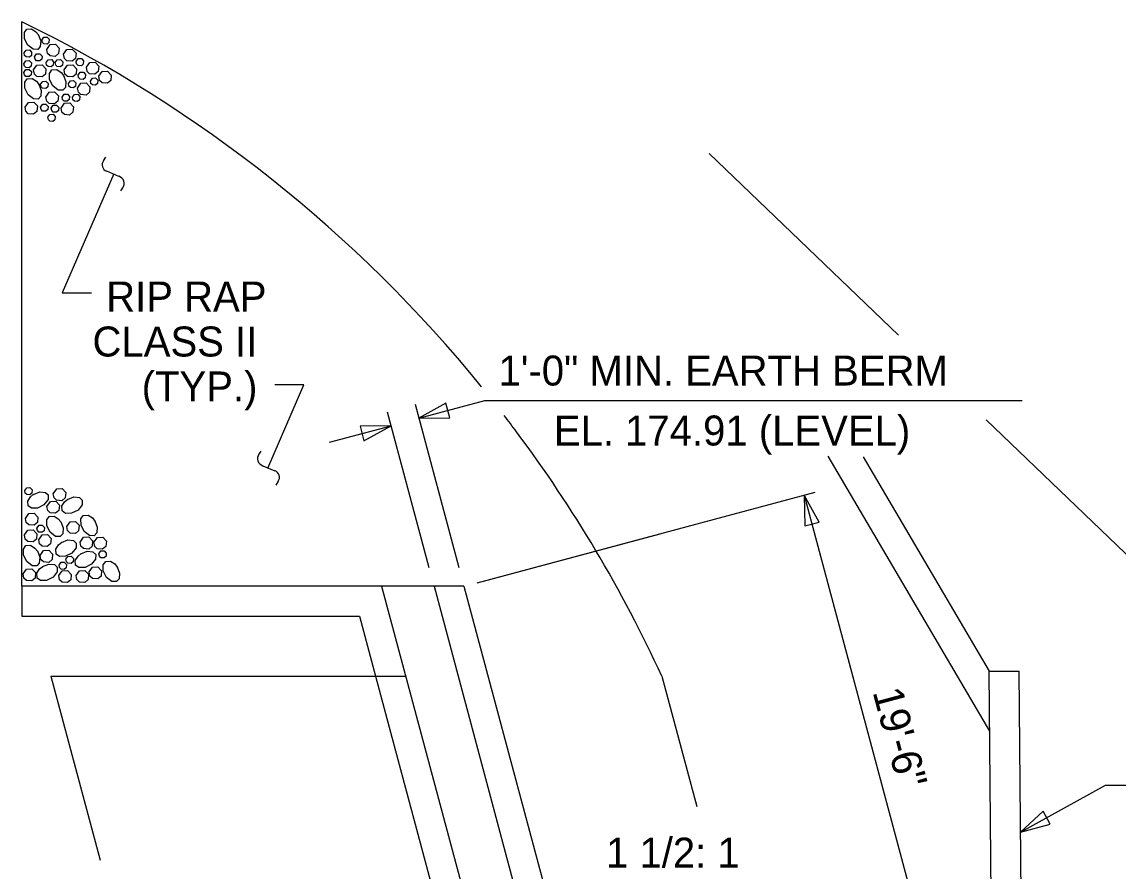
# Model space of a CAD drawing. Extents: x 471 to 2034, y -623 to 126.
# Drawn here: x 624.89 to 661.47, y -12.1 to 16.23 of the extents above; entities that cross this region are included whole.
import ezdxf

# ---------------------------------------------------------------- set-up
doc = ezdxf.new("R2010")
doc.units = 0
for name, color, linetype in [('Arrowhead Terminators CELL', 7, 'Continuous'), ('Dimension Lines', 7, 'Continuous'), ('Exist Hydro Stream or Body of Water', 7, 'Continuous'), ('Exist Structure Major Bridge Seam', 7, 'Continuous'), ('Mis Object Lines', 7, 'Continuous'), ('Mis Object Lines Hidden', 7, 'Continuous'), ('Miscellaneous Lines CELL', 7, 'Continuous'), ('Sup Concrete Girder Lines', 7, 'Continuous'), ('Text', 7, 'Continuous')]:
    doc.layers.add(name, color=color, linetype=linetype)

msp = doc.modelspace()

# ---------------------------------------------------------------- linework, layer by layer
at = {"layer": 'Arrowhead Terminators CELL'}
for p, q in [((627.612, 11.598), (627.687, 11.725)), ((628.124, 11.08), (627.718, 11.255)), ((628.193, 10.601), (628.254, 10.693)), ((632.857, 1.907), (632.797, 1.815)), ((632.927, 1.428), (633.333, 1.252)), ((633.439, 0.909), (633.364, 0.783))]:
    msp.add_line(p, q, dxfattribs=at)
for points in [[(638.138, 3.01), (639.168, 3.028), (639.039, 3.51)], [(637.205, 2.76), (636.174, 2.743), (636.303, 2.26)], [(650.993, 0.447), (650.995, 0.363), (651.034, 0.373)], [(650.993, 0.447), (651.011, -0.584), (651.494, -0.455)], [(658.208, -10.8), (659.204, -10.534), (658.962, -10.097)]]:
    msp.add_lwpolyline(points, close=True, dxfattribs=at)
for centre, radius, start, end in [((627.788, 11.463), 0.221, 142.4705, 250.7561), ((628.052, 10.843), 0.249, 323.4021, 73.201), ((632.999, 1.665), 0.249, 143.4021, 253.201), ((633.262, 1.045), 0.221, 322.4705, 70.7561)]:
    msp.add_arc(centre, radius, start, end, dxfattribs=at)
at = {"layer": 'Dimension Lines'}
for p, q in [((627.951, 11.16), (626.238, 7.195)), ((626.238, 7.195), (627.209, 7.195)), ((633.1, 1.347), (634.298, 4.121)), ((634.298, 4.121), (633.327, 4.121)), ((638.013, 3.475), (639.473, -1.974)), ((638.138, 3.01), (640.341, 3.601)), ((640.341, 3.601), (658.263, 3.601)), ((637.08, 3.225), (638.472, -1.972)), ((635.157, 2.212), (637.205, 2.76)), ((640.076, -2.479), (651.357, 0.544)), ((650.993, 0.447), (655.677, -17.033)), ((640.29, -2.421), (646.187, -0.841)), ((658.208, -10.8), (661.044, -9.229)), ((661.044, -9.229), (662.719, -9.229))]:
    msp.add_line(p, q, dxfattribs=at)
at = {"layer": 'Exist Hydro Stream or Body of Water'}
for points in [[(654.135, 5.777), (647.824, 11.838)], [(665.153, -7.815), (664.7, -4.37), (657.068, 2.96)]]:
    msp.add_lwpolyline(points, dxfattribs=at)
at = {"layer": 'Exist Structure Major Bridge Seam'}
for p, q in [((651.785, 1.747), (657.178, -7.428)), ((652.961, 1.72), (657.16, -5.424)), ((657.16, -5.424), (658.16, -5.424)), ((657.308, -21.967), (657.16, -5.424)), ((658.313, -22.588), (658.16, -5.424))]:
    msp.add_line(p, q, dxfattribs=at)
at = {"layer": 'Mis Object Lines'}
for p, q in [((636.89, -2.596), (646.759, -39.429)), ((638.64, -2.596), (648.509, -39.429)), ((639.64, -2.596), (649.509, -39.429)), ((625.853, -5.596), (627.498, -11.734)), ((625.853, -5.596), (637.693, -5.596))]:
    msp.add_line(p, q, dxfattribs=at)
for points in [[(639.64, -2.596), (624.89, -2.596), (624.89, -3.596), (636.158, -3.596)], [(636.158, -3.596), (636.693, -5.596)]]:
    msp.add_lwpolyline(points, dxfattribs=at)
at = {"layer": 'Mis Object Lines Hidden'}
msp.add_lwpolyline([(636.693, -5.596), (644.955, -36.429)], dxfattribs=at)
at = {"layer": 'Miscellaneous Lines CELL'}
for points in [[(625.437, 15.808), (625.52, 15.599), (625.503, 15.406), (625.416, 15.315), (625.26, 15.318), (625.082, 15.457), (624.975, 15.671), (624.972, 15.873), (625.053, 15.987), (625.214, 15.998), (625.358, 15.906), (625.442, 15.8)], [(625.437, 15.808), (625.52, 15.599), (625.503, 15.406), (625.416, 15.315), (625.26, 15.318), (625.082, 15.457), (624.975, 15.671), (624.972, 15.873), (625.053, 15.987), (625.214, 15.998), (625.358, 15.906), (625.442, 15.8)], [(625.555, 15.627), (625.622, 15.722), (625.73, 15.728), (625.804, 15.651), (625.793, 15.543), (625.727, 15.487), (625.621, 15.495), (625.571, 15.543), (625.555, 15.627)], [(625.555, 15.627), (625.622, 15.722), (625.73, 15.728), (625.804, 15.651), (625.793, 15.543), (625.727, 15.487), (625.621, 15.495), (625.571, 15.543), (625.555, 15.627)], [(625.717, 15.314), (625.829, 15.473), (626.008, 15.484), (626.132, 15.355), (626.114, 15.174), (626.004, 15.082), (625.827, 15.095), (625.744, 15.175), (625.717, 15.314)], [(625.717, 15.314), (625.829, 15.473), (626.008, 15.484), (626.132, 15.355), (626.114, 15.174), (626.004, 15.082), (625.827, 15.095), (625.744, 15.175), (625.717, 15.314)], [(624.965, 15.198), (625.032, 15.293), (625.14, 15.3), (625.214, 15.222), (625.204, 15.114), (625.137, 15.059), (625.031, 15.066), (624.981, 15.115), (624.965, 15.198)], [(624.965, 15.198), (625.032, 15.293), (625.14, 15.3), (625.214, 15.222), (625.204, 15.114), (625.137, 15.059), (625.031, 15.066), (624.981, 15.115), (624.965, 15.198)], [(625.312, 15.07), (625.38, 15.166), (625.487, 15.172), (625.562, 15.094), (625.551, 14.986), (625.485, 14.931), (625.379, 14.938), (625.329, 14.987), (625.313, 15.07)], [(625.312, 15.07), (625.38, 15.166), (625.487, 15.172), (625.562, 15.094), (625.551, 14.986), (625.485, 14.931), (625.379, 14.938), (625.329, 14.987), (625.313, 15.07)], [(626.28, 15.151), (626.392, 15.31), (626.571, 15.321), (626.695, 15.192), (626.677, 15.011), (626.567, 14.919), (626.39, 14.932), (626.307, 15.013), (626.28, 15.151)], [(626.28, 15.151), (626.392, 15.31), (626.571, 15.321), (626.695, 15.192), (626.677, 15.011), (626.567, 14.919), (626.39, 14.932), (626.307, 15.013), (626.28, 15.151)], [(626.7, 14.911), (626.767, 15.007), (626.874, 15.013), (626.949, 14.935), (626.938, 14.827), (626.872, 14.772), (626.766, 14.78), (626.716, 14.828), (626.7, 14.911)], [(626.7, 14.911), (626.767, 15.007), (626.874, 15.013), (626.949, 14.935), (626.938, 14.827), (626.872, 14.772), (626.766, 14.78), (626.716, 14.828), (626.7, 14.911)], [(624.955, 14.837), (625.022, 14.933), (625.129, 14.939), (625.204, 14.862), (625.193, 14.753), (625.127, 14.698), (625.021, 14.706), (624.971, 14.754), (624.955, 14.837)], [(624.955, 14.837), (625.022, 14.933), (625.129, 14.939), (625.204, 14.862), (625.193, 14.753), (625.127, 14.698), (625.021, 14.706), (624.971, 14.754), (624.955, 14.837)], [(624.955, 14.547), (625.022, 14.643), (625.129, 14.649), (625.204, 14.572), (625.193, 14.463), (625.127, 14.408), (625.021, 14.416), (624.971, 14.464), (624.955, 14.547)], [(624.955, 14.547), (625.022, 14.643), (625.129, 14.649), (625.204, 14.572), (625.193, 14.463), (625.127, 14.408), (625.021, 14.416), (624.971, 14.464), (624.955, 14.547)], [(625.278, 14.63), (625.39, 14.789), (625.569, 14.799), (625.693, 14.67), (625.675, 14.49), (625.565, 14.398), (625.388, 14.411), (625.305, 14.491), (625.278, 14.63)], [(625.278, 14.63), (625.39, 14.789), (625.569, 14.799), (625.693, 14.67), (625.675, 14.49), (625.565, 14.398), (625.388, 14.411), (625.305, 14.491), (625.278, 14.63)], [(625.698, 14.875), (625.765, 14.971), (625.873, 14.977), (625.947, 14.9), (625.937, 14.791), (625.87, 14.736), (625.764, 14.744), (625.714, 14.792), (625.698, 14.875)], [(625.698, 14.875), (625.765, 14.971), (625.873, 14.977), (625.947, 14.9), (625.937, 14.791), (625.87, 14.736), (625.764, 14.744), (625.714, 14.792), (625.698, 14.875)], [(626.275, 14.449), (626.358, 14.24), (626.342, 14.047), (626.255, 13.955), (626.098, 13.958), (625.921, 14.097), (625.814, 14.312), (625.81, 14.514), (625.891, 14.628), (626.052, 14.639), (626.196, 14.546), (626.281, 14.441)], [(626.275, 14.449), (626.358, 14.24), (626.342, 14.047), (626.255, 13.955), (626.098, 13.958), (625.921, 14.097), (625.814, 14.312), (625.81, 14.514), (625.891, 14.628), (626.052, 14.639), (626.196, 14.546), (626.281, 14.441)], [(626.002, 14.875), (626.069, 14.971), (626.177, 14.977), (626.251, 14.9), (626.241, 14.791), (626.174, 14.736), (626.068, 14.744), (626.018, 14.792), (626.002, 14.875)], [(626.002, 14.875), (626.069, 14.971), (626.177, 14.977), (626.251, 14.9), (626.241, 14.791), (626.174, 14.736), (626.068, 14.744), (626.018, 14.792), (626.002, 14.875)], [(626.297, 14.63), (626.409, 14.789), (626.588, 14.799), (626.713, 14.67), (626.695, 14.49), (626.584, 14.398), (626.407, 14.411), (626.324, 14.491), (626.297, 14.63)], [(626.297, 14.63), (626.409, 14.789), (626.588, 14.799), (626.713, 14.67), (626.695, 14.49), (626.584, 14.398), (626.407, 14.411), (626.324, 14.491), (626.297, 14.63)], [(627.04, 14.719), (627.152, 14.878), (627.331, 14.889), (627.455, 14.76), (627.437, 14.579), (627.326, 14.487), (627.15, 14.5), (627.067, 14.581), (627.04, 14.719)], [(627.04, 14.719), (627.152, 14.878), (627.331, 14.889), (627.455, 14.76), (627.437, 14.579), (627.326, 14.487), (627.15, 14.5), (627.067, 14.581), (627.04, 14.719)], [(625.452, 14.153), (625.535, 13.943), (625.518, 13.751), (625.431, 13.659), (625.275, 13.662), (625.097, 13.801), (624.99, 14.016), (624.987, 14.218), (625.067, 14.332), (625.229, 14.343), (625.373, 14.25), (625.457, 14.144)], [(625.452, 14.153), (625.535, 13.943), (625.518, 13.751), (625.431, 13.659), (625.275, 13.662), (625.097, 13.801), (624.99, 14.016), (624.987, 14.218), (625.067, 14.332), (625.229, 14.343), (625.373, 14.25), (625.457, 14.144)], [(626.439, 14.172), (626.506, 14.267), (626.614, 14.273), (626.688, 14.196), (626.678, 14.088), (626.611, 14.032), (626.505, 14.04), (626.455, 14.088), (626.439, 14.172)], [(626.439, 14.172), (626.506, 14.267), (626.614, 14.273), (626.688, 14.196), (626.678, 14.088), (626.611, 14.032), (626.505, 14.04), (626.455, 14.088), (626.439, 14.172)], [(626.764, 14.455), (626.832, 14.551), (626.939, 14.557), (627.013, 14.48), (627.003, 14.371), (626.936, 14.316), (626.83, 14.324), (626.781, 14.372), (626.764, 14.455)], [(626.764, 14.455), (626.832, 14.551), (626.939, 14.557), (627.013, 14.48), (627.003, 14.371), (626.936, 14.316), (626.83, 14.324), (626.781, 14.372), (626.764, 14.455)], [(627.175, 14.26), (627.242, 14.356), (627.35, 14.362), (627.424, 14.285), (627.413, 14.176), (627.347, 14.121), (627.241, 14.129), (627.191, 14.177), (627.175, 14.26)], [(627.175, 14.26), (627.242, 14.356), (627.35, 14.362), (627.424, 14.285), (627.413, 14.176), (627.347, 14.121), (627.241, 14.129), (627.191, 14.177), (627.175, 14.26)], [(627.455, 14.417), (627.567, 14.577), (627.746, 14.587), (627.871, 14.458), (627.853, 14.277), (627.742, 14.185), (627.565, 14.198), (627.482, 14.279), (627.455, 14.417)], [(627.455, 14.417), (627.567, 14.577), (627.746, 14.587), (627.871, 14.458), (627.853, 14.277), (627.742, 14.185), (627.565, 14.198), (627.482, 14.279), (627.455, 14.417)], [(625.515, 14.154), (625.582, 14.249), (625.689, 14.255), (625.764, 14.178), (625.753, 14.07), (625.687, 14.014), (625.581, 14.022), (625.531, 14.07), (625.515, 14.154)], [(625.515, 14.154), (625.582, 14.249), (625.689, 14.255), (625.764, 14.178), (625.753, 14.07), (625.687, 14.014), (625.581, 14.022), (625.531, 14.07), (625.515, 14.154)], [(626.746, 14.025), (626.858, 14.184), (627.037, 14.195), (627.161, 14.066), (627.143, 13.885), (627.033, 13.793), (626.856, 13.806), (626.773, 13.886), (626.746, 14.025)], [(626.746, 14.025), (626.858, 14.184), (627.037, 14.195), (627.161, 14.066), (627.143, 13.885), (627.033, 13.793), (626.856, 13.806), (626.773, 13.886), (626.746, 14.025)], [(624.993, 13.388), (625.105, 13.547), (625.284, 13.558), (625.409, 13.429), (625.391, 13.248), (625.28, 13.156), (625.103, 13.169), (625.02, 13.249), (624.993, 13.388)], [(624.993, 13.388), (625.105, 13.547), (625.284, 13.558), (625.409, 13.429), (625.391, 13.248), (625.28, 13.156), (625.103, 13.169), (625.02, 13.249), (624.993, 13.388)], [(625.691, 13.726), (625.803, 13.885), (625.982, 13.896), (626.106, 13.767), (626.088, 13.586), (625.978, 13.494), (625.801, 13.507), (625.718, 13.587), (625.691, 13.726)], [(625.691, 13.726), (625.803, 13.885), (625.982, 13.896), (626.106, 13.767), (626.088, 13.586), (625.978, 13.494), (625.801, 13.507), (625.718, 13.587), (625.691, 13.726)], [(626.23, 13.724), (626.298, 13.819), (626.405, 13.826), (626.48, 13.748), (626.469, 13.64), (626.403, 13.585), (626.297, 13.592), (626.247, 13.641), (626.231, 13.724)], [(626.23, 13.724), (626.298, 13.819), (626.405, 13.826), (626.48, 13.748), (626.469, 13.64), (626.403, 13.585), (626.297, 13.592), (626.247, 13.641), (626.231, 13.724)], [(626.575, 13.719), (626.642, 13.815), (626.75, 13.821), (626.824, 13.744), (626.814, 13.635), (626.747, 13.58), (626.641, 13.588), (626.591, 13.636), (626.575, 13.719)], [(626.575, 13.719), (626.642, 13.815), (626.75, 13.821), (626.824, 13.744), (626.814, 13.635), (626.747, 13.58), (626.641, 13.588), (626.591, 13.636), (626.575, 13.719)], [(625.515, 13.389), (625.582, 13.484), (625.689, 13.49), (625.764, 13.413), (625.753, 13.305), (625.687, 13.25), (625.581, 13.257), (625.531, 13.306), (625.515, 13.389)], [(625.515, 13.389), (625.582, 13.484), (625.689, 13.49), (625.764, 13.413), (625.753, 13.305), (625.687, 13.25), (625.581, 13.257), (625.531, 13.306), (625.515, 13.389)], [(625.869, 13.355), (625.936, 13.451), (626.044, 13.457), (626.118, 13.38), (626.107, 13.271), (626.041, 13.216), (625.935, 13.224), (625.885, 13.272), (625.869, 13.355)], [(625.869, 13.355), (625.936, 13.451), (626.044, 13.457), (626.118, 13.38), (626.107, 13.271), (626.041, 13.216), (625.935, 13.224), (625.885, 13.272), (625.869, 13.355)], [(626.195, 13.358), (626.307, 13.518), (626.486, 13.528), (626.61, 13.399), (626.592, 13.218), (626.482, 13.126), (626.305, 13.139), (626.222, 13.22), (626.195, 13.358)], [(626.195, 13.358), (626.307, 13.518), (626.486, 13.528), (626.61, 13.399), (626.592, 13.218), (626.482, 13.126), (626.305, 13.139), (626.222, 13.22), (626.195, 13.358)], [(625.754, 13.051), (625.822, 13.147), (625.929, 13.153), (626.003, 13.075), (625.993, 12.967), (625.926, 12.912), (625.82, 12.92), (625.771, 12.968), (625.754, 13.051)], [(625.754, 13.051), (625.822, 13.147), (625.929, 13.153), (626.003, 13.075), (625.993, 12.967), (625.926, 12.912), (625.82, 12.92), (625.771, 12.968), (625.754, 13.051)], [(624.982, 0.595), (625.05, 0.69), (625.157, 0.696), (625.232, 0.619), (625.221, 0.511), (625.155, 0.455), (625.049, 0.463), (624.999, 0.512), (624.983, 0.595)], [(625.273, 0.472), (625.482, 0.555), (625.675, 0.538), (625.766, 0.451), (625.764, 0.295), (625.625, 0.118), (625.41, 0.01), (625.208, 0.007), (625.094, 0.088), (625.083, 0.249), (625.175, 0.393), (625.281, 0.477)], [(625.937, 0.492), (626.049, 0.652), (626.228, 0.662), (626.352, 0.533), (626.334, 0.352), (626.223, 0.26), (626.047, 0.273), (625.964, 0.354), (625.937, 0.492)], [(626.412, 0.302), (626.621, 0.386), (626.814, 0.369), (626.905, 0.282), (626.902, 0.126), (626.763, -0.052), (626.549, -0.159), (626.346, -0.163), (626.233, -0.082), (626.222, 0.079), (626.314, 0.223), (626.42, 0.308)], [(625.726, 0.071), (625.838, 0.23), (626.017, 0.24), (626.141, 0.111), (626.123, -0.069), (626.013, -0.161), (625.836, -0.148), (625.753, -0.068), (625.726, 0.071)], [(625.007, -0.329), (625.119, -0.17), (625.298, -0.16), (625.423, -0.289), (625.405, -0.469), (625.294, -0.561), (625.117, -0.548), (625.034, -0.468), (625.007, -0.329)], [(626.184, -0.442), (626.267, -0.651), (626.25, -0.844), (626.163, -0.936), (626.007, -0.933), (625.829, -0.794), (625.722, -0.579), (625.718, -0.377), (625.799, -0.263), (625.96, -0.252), (626.104, -0.344), (626.189, -0.45)], [(627.322, -0.415), (627.405, -0.624), (627.389, -0.817), (627.302, -0.908), (627.146, -0.905), (626.968, -0.767), (626.861, -0.552), (626.857, -0.35), (626.938, -0.236), (627.099, -0.225), (627.243, -0.317), (627.328, -0.423)], [(624.976, -0.883), (625.088, -0.723), (625.267, -0.713), (625.391, -0.842), (625.373, -1.023), (625.263, -1.115), (625.086, -1.102), (625.003, -1.021), (624.976, -0.883)], [(625.392, -0.656), (625.46, -0.56), (625.567, -0.554), (625.641, -0.631), (625.631, -0.74), (625.564, -0.795), (625.458, -0.787), (625.409, -0.739), (625.392, -0.656)], [(626.385, -0.6), (626.497, -0.441), (626.676, -0.431), (626.8, -0.56), (626.782, -0.74), (626.672, -0.832), (626.495, -0.82), (626.412, -0.739), (626.385, -0.6)], [(625.449, -1.041), (625.561, -0.882), (625.74, -0.871), (625.865, -1), (625.847, -1.181), (625.736, -1.273), (625.56, -1.26), (625.476, -1.18), (625.449, -1.041)], [(626.208, -1.135), (626.418, -1.051), (626.61, -1.068), (626.702, -1.155), (626.699, -1.311), (626.56, -1.489), (626.345, -1.596), (626.143, -1.6), (626.029, -1.519), (626.018, -1.358), (626.111, -1.214), (626.217, -1.129)], [(626.833, -1.12), (626.945, -0.961), (627.124, -0.95), (627.249, -1.079), (627.231, -1.26), (627.12, -1.352), (626.943, -1.339), (626.86, -1.258), (626.833, -1.12)], [(627.294, -1.127), (627.406, -0.967), (627.585, -0.957), (627.709, -1.086), (627.691, -1.267), (627.581, -1.359), (627.404, -1.346), (627.321, -1.265), (627.294, -1.127)], [(625.404, -1.418), (625.487, -1.627), (625.47, -1.82), (625.383, -1.912), (625.227, -1.909), (625.05, -1.77), (624.942, -1.555), (624.939, -1.353), (625.02, -1.239), (625.181, -1.228), (625.325, -1.32), (625.409, -1.426)], [(625.499, -1.565), (625.611, -1.406), (625.79, -1.396), (625.915, -1.525), (625.897, -1.705), (625.786, -1.797), (625.609, -1.785), (625.526, -1.704), (625.499, -1.565)], [(626.859, -1.509), (627.068, -1.426), (627.261, -1.443), (627.352, -1.53), (627.349, -1.686), (627.21, -1.863), (626.996, -1.971), (626.793, -1.974), (626.68, -1.893), (626.669, -1.732), (626.761, -1.588), (626.867, -1.504)], [(627.457, -1.512), (627.524, -1.417), (627.632, -1.41), (627.706, -1.488), (627.696, -1.596), (627.629, -1.651), (627.523, -1.644), (627.473, -1.595), (627.457, -1.512)], [(626.128, -1.891), (626.195, -1.795), (626.302, -1.789), (626.377, -1.866), (626.366, -1.975), (626.3, -2.03), (626.194, -2.022), (626.144, -1.974), (626.128, -1.891)], [(626.359, -1.696), (626.426, -1.6), (626.534, -1.594), (626.608, -1.672), (626.597, -1.78), (626.531, -1.835), (626.425, -1.828), (626.375, -1.779), (626.359, -1.696)], [(628.068, -1.947), (628.151, -2.156), (628.134, -2.349), (628.047, -2.44), (627.891, -2.437), (627.714, -2.298), (627.606, -2.084), (627.603, -1.882), (627.684, -1.768), (627.845, -1.757), (627.989, -1.849), (628.073, -1.955)], [(624.931, -2.182), (625.043, -2.022), (625.222, -2.012), (625.347, -2.141), (625.329, -2.322), (625.218, -2.414), (625.042, -2.401), (624.958, -2.32), (624.932, -2.182)], [(625.578, -1.936), (625.787, -1.853), (625.98, -1.869), (626.071, -1.957), (626.068, -2.113), (625.929, -2.29), (625.715, -2.398), (625.512, -2.401), (625.399, -2.32), (625.388, -2.159), (625.48, -2.015), (625.586, -1.931)], [(626.12, -2.241), (626.232, -2.081), (626.411, -2.071), (626.536, -2.2), (626.518, -2.381), (626.407, -2.473), (626.231, -2.46), (626.147, -2.379), (626.121, -2.241)], [(626.699, -2.234), (626.811, -2.075), (626.989, -2.065), (627.114, -2.194), (627.096, -2.374), (626.985, -2.466), (626.809, -2.453), (626.726, -2.373), (626.699, -2.234)], [(627.133, -2.117), (627.245, -1.958), (627.424, -1.948), (627.548, -2.077), (627.53, -2.257), (627.42, -2.349), (627.243, -2.336), (627.16, -2.256), (627.133, -2.117)]]:
    msp.add_lwpolyline(points, dxfattribs=at)
at = {"layer": 'Sup Concrete Girder Lines'}
for p, q in [((624.89, -2.596), (624.89, 16.231)), ((624.89, -2.596), (624.89, 16.231)), ((646.241, -5.596), (647.405, -9.94))]:
    msp.add_line(p, q, dxfattribs=at)
for start, end in [(39.1222, 64.0036), (36.716, 37.582), (24.7352, 36.716)]:
    msp.add_arc((604.975, -24.607), 45.435, start, end, dxfattribs=at)

# ---------------------------------------------------------------- texts
at = {"layer": 'Text'}
for s, p in [('RIP RAP', (627.701, 6.57)), ('CLASS II', (627.244, 5.07)), ('1\'-0" MIN. EARTH BERM', (640.792, 4.101)), ('(TYP.)', (628.886, 3.57)), ('EL. 174.91 (LEVEL)', (642.638, 2.101)), ('1 1/2: 1', (644.38, -11.981)), ('1 1/2: 1', (644.38, -11.981))]:
    msp.add_text(s, height=1, dxfattribs=at).set_placement(p)
msp.add_text('19\'-6"', height=1, rotation=285, dxfattribs=at).set_placement((653.27, -6.118))

doc.saveas('drawing.dxf')
